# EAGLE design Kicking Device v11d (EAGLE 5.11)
MFG_PART: 74404052470; OC_DIGIKEY: 732-7252-1-ND; OC_FARNELL: 2062831

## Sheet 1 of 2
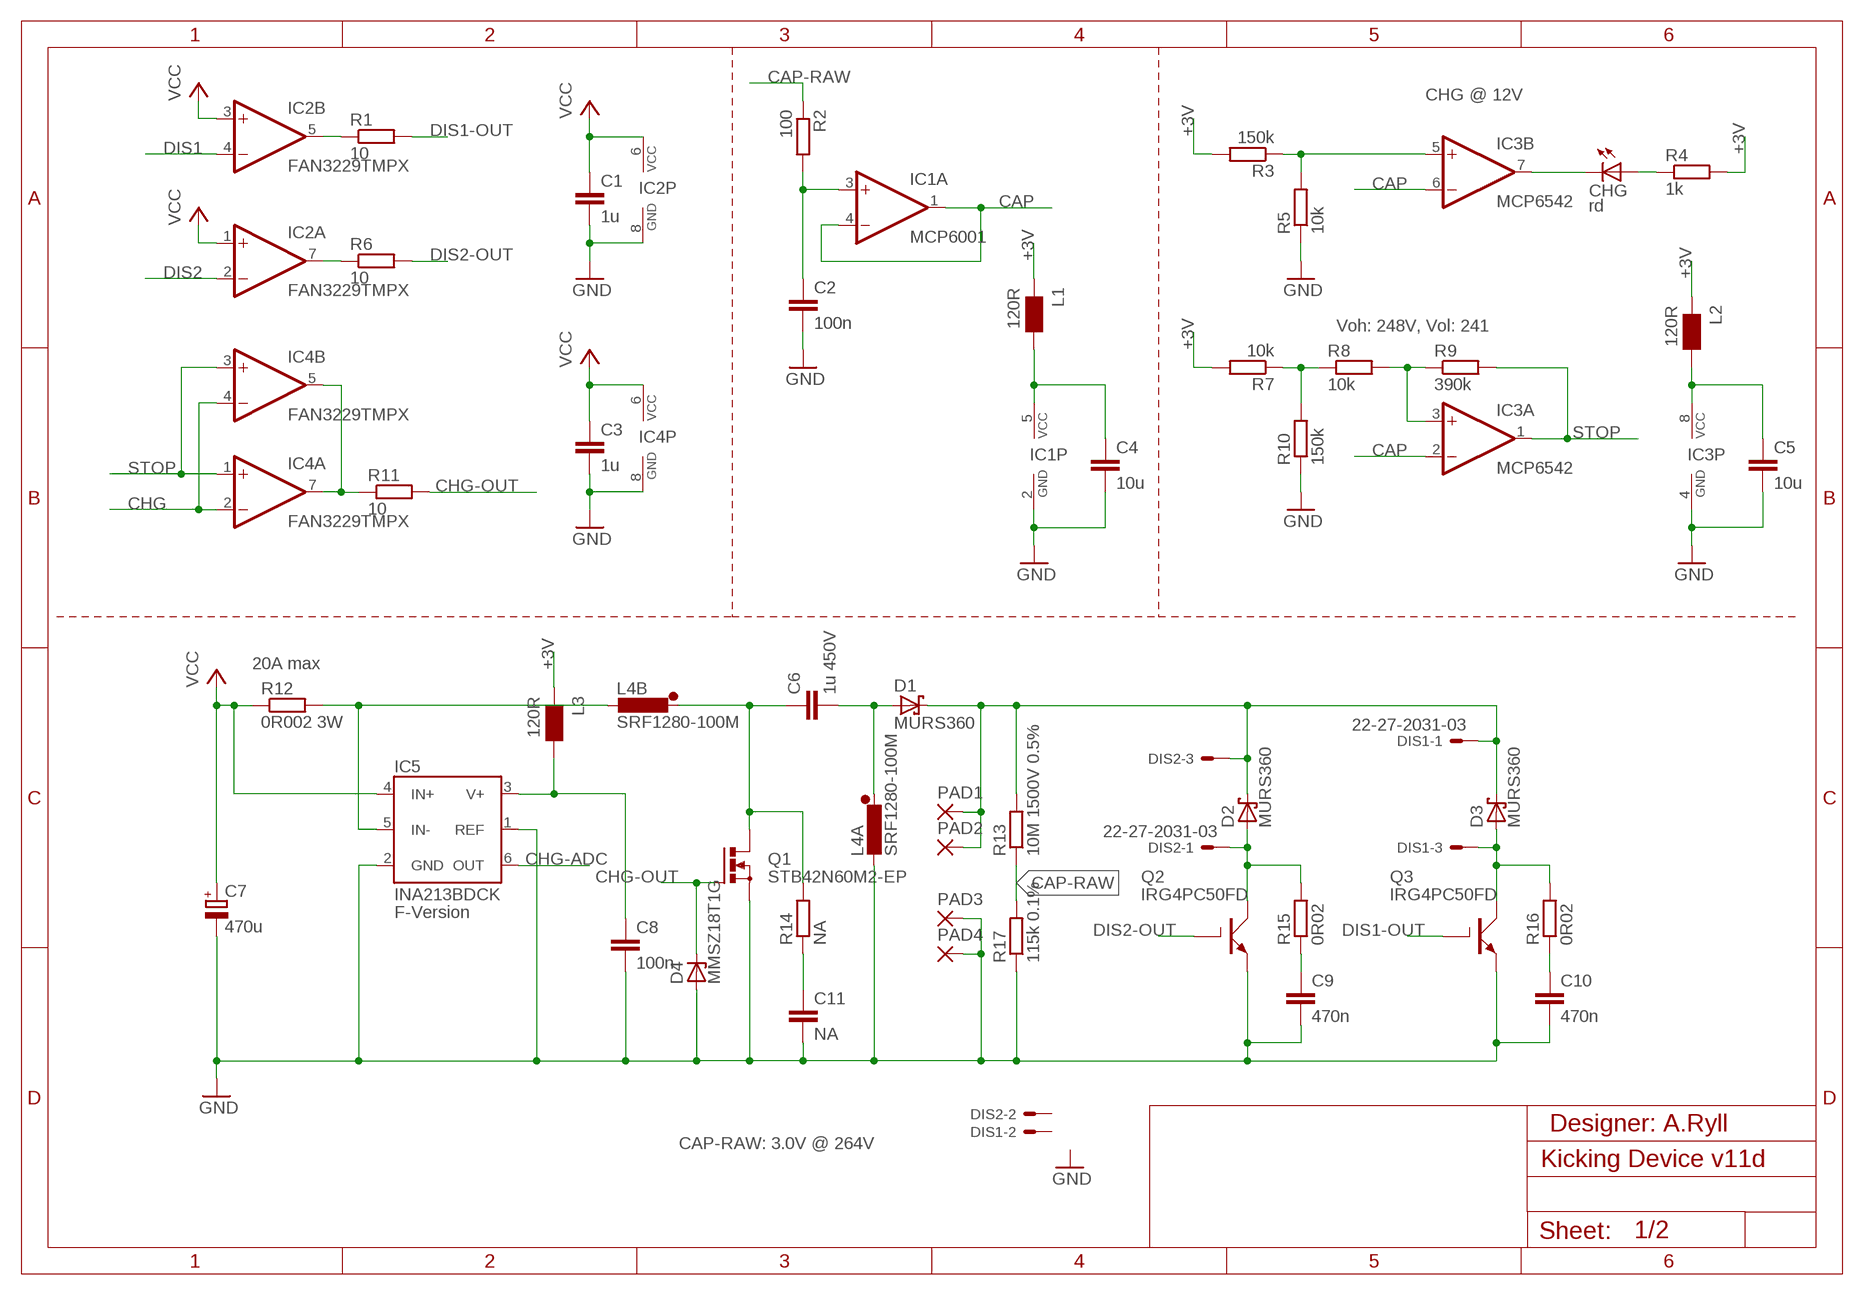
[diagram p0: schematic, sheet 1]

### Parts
C1  1u  C-EUC0603  [C0603]
C2  100n  C-EUC0603  [C0603]
C3  1u  C-EUC0603  [C0603]
C4  10u  C-EUC0603  [C0603]
C5  10u  C-EUC0603  [C0603]
C6  1u 450V  C-EUC2220K  [C2220K]
C7  470u  CPOL-EUG  [PANASONIC_G]
C8  100n  C-EUC0603  [C0603]
C9  470n  C-EUC1812  [C1812]
C10  470n  C-EUC1812  [C1812]
C11  NA  C-EUC1206  [C1206]
CHG  rd  LEDCHIP-LED0603  [CHIP-LED0603]
D1  MURS360  SCHOTTKY-DIODESMC  [SMC]
D2  MURS360  SCHOTTKY-DIODESMC  [SMC]
D3  MURS360  SCHOTTKY-DIODESMC  [SMC]
D4  MMSZ18T1G  ZENER-DIODESOD80C  [SOD80C]
DIS1  22-27-2031-03  [6410-03]
DIS2  22-27-2031-03  [6410-03]
IC1  MCP6001  AD-OP1RT  [SOT23-5]
IC2  FAN3229TMPX  FAN3229_MP  [MLP8]
IC3  MCP6542  AD-OP2M  [MSOP8]
IC4  FAN3229TMPX  FAN3229_MP  [MLP8]
IC5  INA213BDCK  INA21XDCK  [SC70-6L]
L1  120R  WE-CBF_0603  [0603]
L2  120R  WE-CBF_0603  [0603]
L3  120R  WE-CBF_0603  [0603]
L4  SRF1280-100M  SRF1280  [SRF1280]
PAD1  SMD5  [SMD2,54-5,08]
PAD2  SMD5  [SMD2,54-5,08]
PAD3  SMD5  [SMD2,54-5,08]
PAD4  SMD5  [SMD2,54-5,08]
Q1  STB42N60M2-EP  NMOS-D2PAK  [D2PAK]
Q2  IRG4PC50FD  IGBTTO247BV  [TO247BV]
Q3  IRG4PC50FD  IGBTTO247BV  [TO247BV]
R1  10  R-EU_R0603  [R0603]
R2  100  R-EU_R0603  [R0603]
R3  150k  R-EU_R0603  [R0603]
R4  1k  R-EU_R0603  [R0603]
R5  10k  R-EU_R0603  [R0603]
R6  10  R-EU_R0603  [R0603]
R7  10k  R-EU_R0603  [R0603]
R8  10k  R-EU_R0603  [R0603]
R9  390k  R-EU_R0603  [R0603]
R10  150k  R-EU_R0603  [R0603]
R11  10  R-EU_R0603  [R0603]
R12  0R002 3W  R-EU_R2512  [R2512]
R13  10M 1500V 0.5%  R-EU_R1206  [R1206]
R14  NA  R-EU_R1206  [R1206]
R15  0R02  R-EU_R1206  [R1206]
R16  0R02  R-EU_R1206  [R1206]
R17  115k 0.1%  R-EU_R1206  [R1206]

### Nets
400-SW: IC5.5(IN-) L4.P$4 R12.2
+3V: L1.1 L2.1 L3.1 R3.2 R4.2 R7.2 ; also sheet 2
CAP: IC1.1(A:OUT) IC1.4(A:-IN) IC3.2(A:-IN) IC3.6(B:-IN) ; also sheet 2
CAP-RAW: R2.1 R13.1 R17.2
CAPVCC [HV]: D1.C D2.C D3.C DIS1.1 DIS2.3 PAD1.1(P) PAD2.1(P) R13.2
CHG: IC4.2(A:-IN) IC4.4(B:-IN) ; also sheet 2
CHG-ADC: IC5.6(OUT) ; also sheet 2
CHG-OUT: D4.C Q1.1(G) R11.2
CMP-VCC: C5.1 IC3.8(P:VCC) L2.2
DIS1: IC2.4(B:-IN) ; also sheet 2
DIS1-OUT: Q3.1(G) R1.2
DIS1-SW [HV]: D2.A DIS2.1 Q2.2(C) R15.2
DIS2: IC2.2(A:-IN) ; also sheet 2
DIS2-OUT: Q2.1(G) R6.2
DIS2-SW [HV]: D3.A DIS1.3 Q3.2(C) R16.2
GND: C1.2 C2.2 C3.2 C4.2 C5.2 C7.- C8.2 C9.2 C10.2 C11.2 D4.A IC1.2(P:GND) IC2.8(P:GND) IC3.4(P:GND) IC4.8(P:GND) IC5.1(REF) IC5.2(GND) L4.P$3 PAD3.1(P) PAD4.1(P) Q1.3(S) Q2.3(E) Q3.3(E) R5.1 R10.1 R17.1 ; also sheet 2
INA-VCC: C8.1 IC5.3(V+) L3.2
N$2: IC3.5(B:+IN) R3.1 R5.2
N$3: R7.1 R8.1 R10.2
N$4: CHG.C IC3.7(B:OUT)
N$5: IC2.5(B:OUT) R1.1
N$6: CHG.A R4.1
N$8: IC3.3(A:+IN) R8.2 R9.1
N$10: C6.1 L4.P$2 Q1.2(D) R14.2
N$12: C2.1 IC1.3(A:+IN) R2.2
N$13: C6.2 D1.A L4.P$1
N$14: IC4.5(B:OUT) IC4.7(A:OUT) R11.1
N$17: IC2.7(A:OUT) R6.1
N$19: C10.1 R16.1
N$20: C9.1 R15.1
N$21: C11.1 R14.1
OP-VCC: C4.1 IC1.5(P:VCC) L1.2
STOP: IC3.1(A:OUT) IC4.1(A:+IN) IC4.3(B:+IN) R9.2 ; also sheet 2
VCC: C1.1 C3.1 C7.+ IC2.1(A:+IN) IC2.3(B:+IN) IC2.6(P:VCC) IC4.6(P:VCC) IC5.4(IN+) R12.1 ; also sheet 2
Unconnected: DIS1.2 DIS2.2

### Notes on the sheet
- CHG @ 12V
- Voh: 248V, Vol: 241
- 20A max
- F-Version
- Designer: A.Ryll
- CAP-RAW: 3.0V @ 264V

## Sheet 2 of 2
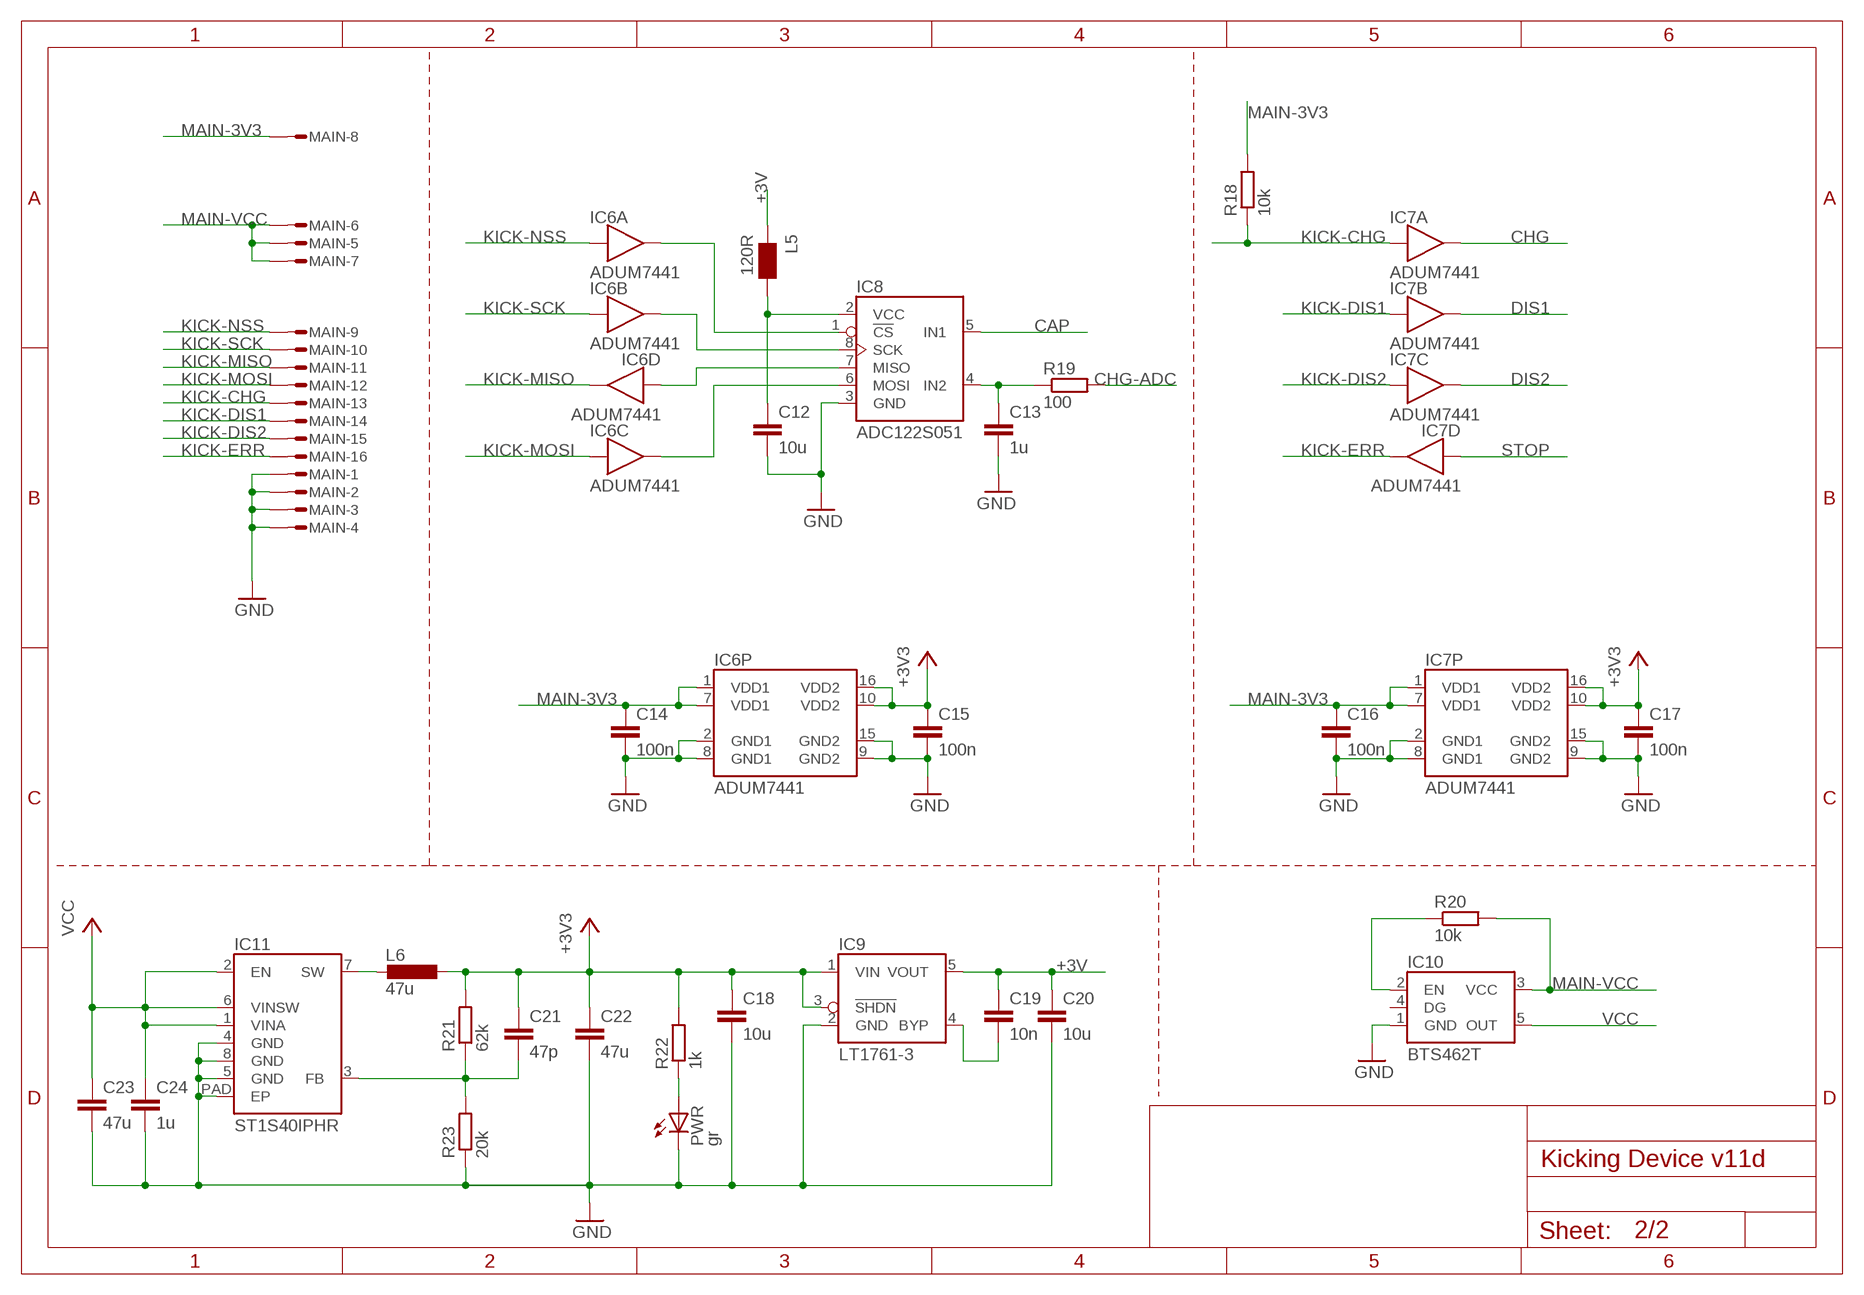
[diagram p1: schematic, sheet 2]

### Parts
C12  10u  C-EUC0603  [C0603]
C13  1u  C-EUC0603  [C0603]
C14  100n  C-EUC0603  [C0603]
C15  100n  C-EUC0603  [C0603]
C16  100n  C-EUC0603  [C0603]
C17  100n  C-EUC0603  [C0603]
C18  10u  C-EUC0603  [C0603]
C19  10n  C-EUC0603  [C0603]
C20  10u  C-EUC0603  [C0603]
C21  47p  C-EUC0603  [C0603]
C22  47u  C-EUC1206  [C1206]
C23  47u  C-EUC1206  [C1206]
C24  1u  C-EUC0603  [C0603]
IC6  ADUM7441  [QSOP16]
IC7  ADUM7441  [QSOP16]
IC8  ADC122S051  ADC__2S__1  [MSOP8]
IC9  LT1761-3  LT1761  [SOT23-5]
IC10  BTS462T  IPS6021R  [TO252-51]
IC11  ST1S40IPHR  [HSOP8]
L5  120R  WE-CBF_0603  [0603]
L6  47u  LLQS  [WE-LQS]
MAIN  MICROMATCH-16SMF  [MMT-F-SMD-16]
PWR  gr  LEDCHIP-LED0603  [CHIP-LED0603]
R18  10k  R-EU_R0603  [R0603]
R19  100  R-EU_R0603  [R0603]
R20  10k  R-EU_R0603  [R0603]
R21  62k  R-EU_R0603  [R0603]
R22  1k  R-EU_R0603  [R0603]
R23  20k  R-EU_R0603  [R0603]

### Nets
+3V: C19.1 C20.1 IC9.5(VOUT) L5.1 ; also sheet 1
+3V3: C15.1 C17.1 C18.1 C21.1 C22.1 IC6.10(P:VDD2) IC6.16(P:VDD2) IC7.10(P:VDD2) IC7.16(P:VDD2) IC9.1(VIN) IC9.3(!SHDN) L6.1 R21.2 R22.2
ADC-VCC: C12.1 IC8.2(VCC) L5.2
CAP: IC8.5(IN1) ; also sheet 1
CHG: IC7.14(A:OUT) ; also sheet 1
CHG-ADC: R19.2 ; also sheet 1
DIS1: IC7.13(B:OUT) ; also sheet 1
DIS2: IC7.12(C:OUT) ; also sheet 1
FB1: C21.2 IC11.3(FB) R21.1 R23.2
GND: C12.2 C13.2 C14.2 C15.2 C16.2 C17.2 C18.2 C20.2 C22.2 C23.2 C24.2 IC6.2(P:GND1) IC6.8(P:GND1) IC6.9(P:GND2) IC6.15(P:GND2) IC7.2(P:GND1) IC7.8(P:GND1) IC7.9(P:GND2) IC7.15(P:GND2) IC8.3(GND) IC9.2(GND) IC10.1(GND) IC11.4(GND) IC11.5(GND) IC11.8(GND) IC11.PAD(EP) MAIN.1 MAIN.2 MAIN.3 MAIN.4 PWR.C R23.1 ; also sheet 1
KICK-CHG: IC7.3(A:IN) MAIN.13 R18.1
KICK-DIS1: IC7.4(B:IN) MAIN.14
KICK-DIS2: IC7.5(C:IN) MAIN.15
KICK-ERR: IC7.6(D:OUT) MAIN.16
KICK-MISO: IC6.6(D:OUT) MAIN.11
KICK-MOSI: IC6.5(C:IN) MAIN.12
KICK-NSS: IC6.3(A:IN) MAIN.9
KICK-SCK: IC6.4(B:IN) MAIN.10
MAIN-3V3: C14.1 C16.1 IC6.1(P:VDD1) IC6.7(P:VDD1) IC7.1(P:VDD1) IC7.7(P:VDD1) MAIN.8 R18.2
MAIN-VCC: IC10.3(VCC) MAIN.5 MAIN.6 MAIN.7 R20.2
N$1: IC6.13(B:OUT) IC8.8(SCK)
N$7: IC6.11(D:IN) IC8.7(MISO)
N$9: PWR.A R22.1
N$11: IC10.2(EN) R20.1
N$15: IC6.12(C:OUT) IC8.6(MOSI)
N$16: IC6.14(A:OUT) IC8.1(!CS)
N$18: C13.1 IC8.4(IN2) R19.1
N$22: C19.2 IC9.4(BYP)
STOP: IC7.11(D:IN) ; also sheet 1
SW1: IC11.7(SW) L6.2
VCC: C23.1 C24.1 IC10.5(OUT) IC11.1(VINA) IC11.2(EN) IC11.6(VINSW) ; also sheet 1
Unconnected: IC10.4(DG)

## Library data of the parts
C1-C6 C8-C24 = rcl:C-EU: CAPACITOR, European symbol
C7 = rcl:CPOL-EU: POLARIZED CAPACITOR, European symbol
CHG PWR = led:LED: LED
D1-D3 = diode:SCHOTTKY-DIODE: Schottky Diode
D4 = diode:ZENER-DIODE: Z-Diode
DIS1 DIS2 = con-molex:22-?-03: CONNECTOR wire to board 2.54 mm (.1 inch) pitch header
IC1 = Marvin:AD-OP1
IC2 IC4 = Marvin:FAN322
IC3 = Marvin:AD-OP2
IC5 = Marvin:INA21X
IC6 IC7 = Marvin:ADUM744
IC8 = Marvin:ADC__2S__1
IC9 = Marvin:LT1761
IC10 = Marvin:IPS60
IC11 = Marvin:ST1S40IP
L1-L3 L5 = wuerth-elektronik:WE-CBF: SMD EMI Suppression Ferrite Beads
L4 = Marvin:SRF
L6 = Marvin:L
MAIN = con-amp-micromatch:MICROMATCH-16: MicroMaTch 16 8-215464-6 / 1-215464-6 Drawing Number C-215464 DDEController.pdf
PAD1-PAD4 = wirepad:SMD5: SMD PAD
Q1 = Marvin:NMOS-D2PAK
Q2 Q3 = Marvin:IGBT
R1-R23 = rcl:R-EU_: RESISTOR, European symbol

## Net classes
0 default: width 0.152 mm, clearance 0.152 mm
1 HV: width 0.203 mm, drill 0.305 mm, clearance 1.016 mm to class 0, clearance 1.016 mm

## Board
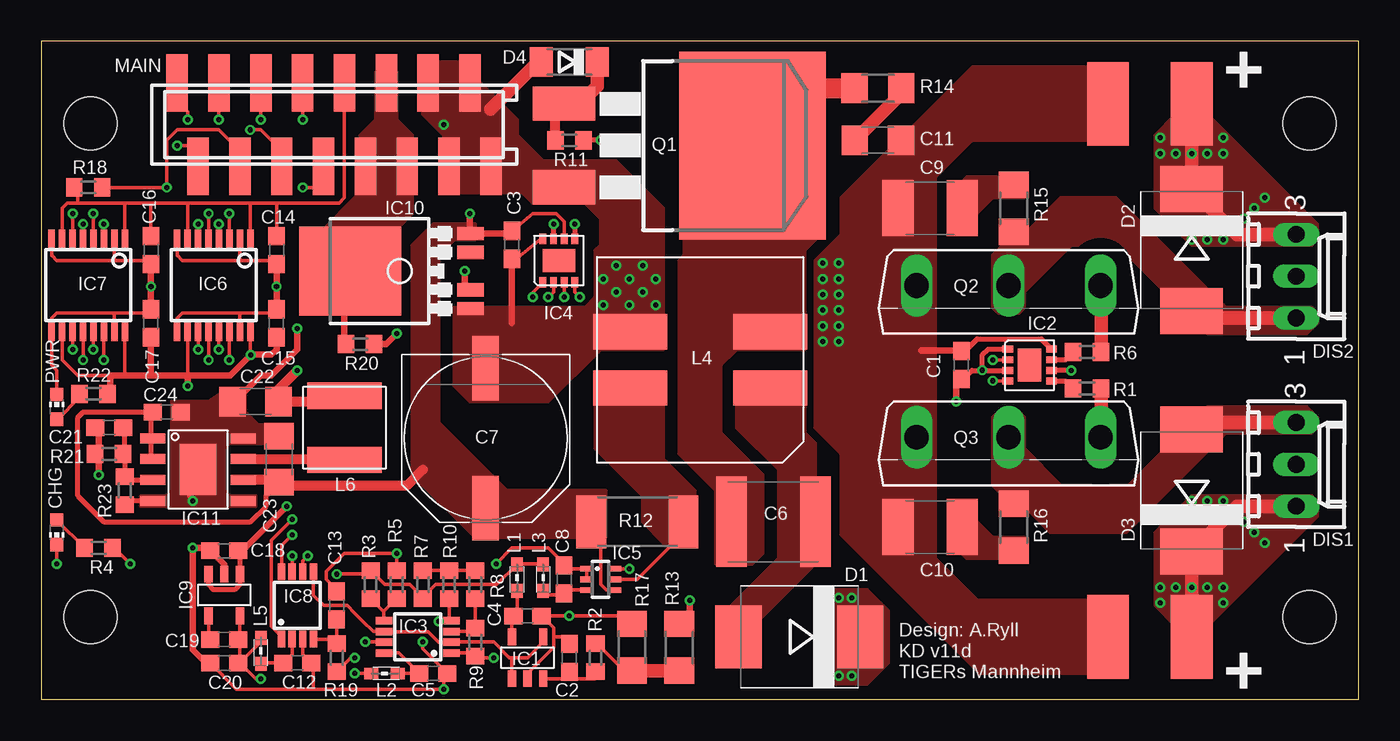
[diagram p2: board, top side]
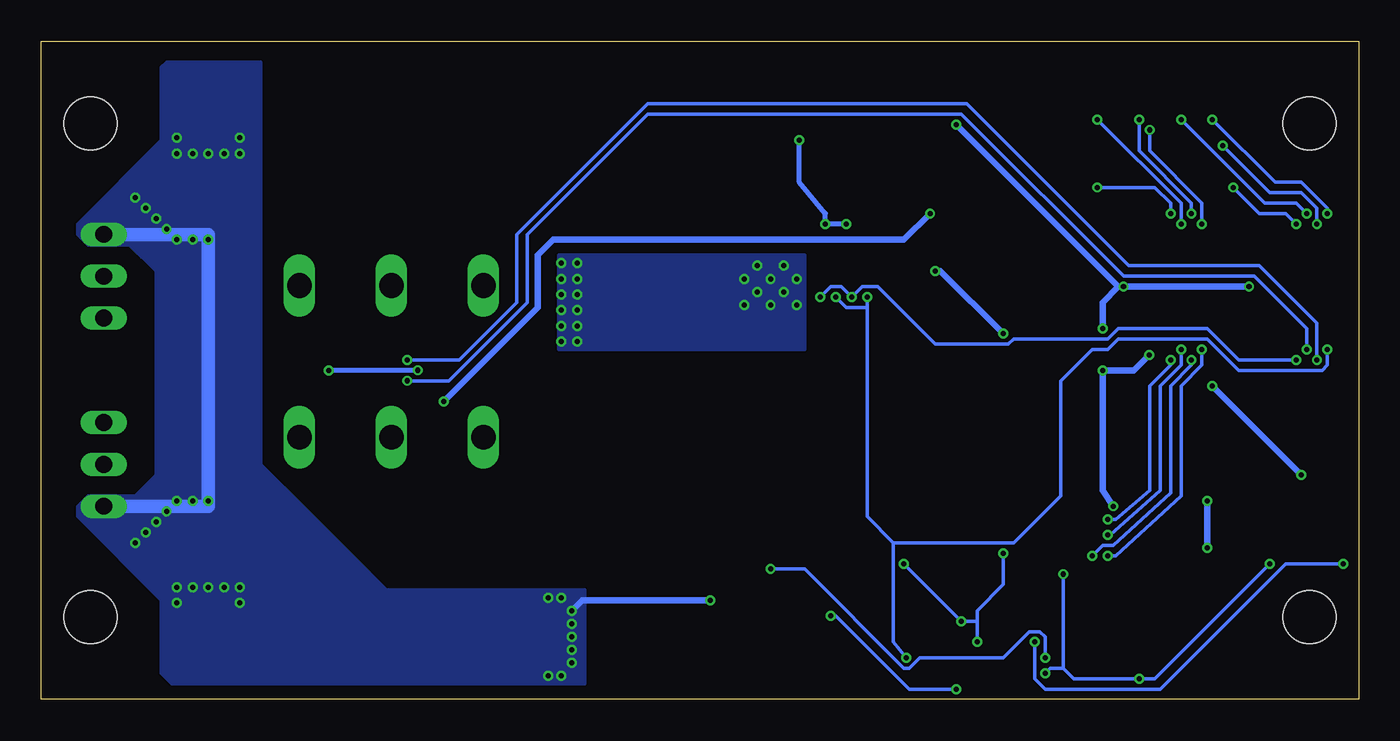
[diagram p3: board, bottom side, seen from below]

Size 80 x 40 mm. Coordinates in mm from the lower left corner, seen from the top.
Outline: 0,0 80,0 80,40 0,40 0,0
Copper layers (1*16): Top 0.035mm / dielectric 1.5mm / Bottom 0.035mm
Design rules "PCB-POOL Standard *": minimum track width 0.15mm, minimum drill 0.3mm, track to track 0.15mm, track to pad 0.15mm, pad to pad 0.15mm, via to via 0.15mm, smd to smd 0.15mm, copper to edge 0.3mm, drill to drill 0.2mm, minimum pad ring 0.2mm, minimum via ring 0.15mm, stop-mask expansion 0.075mm, vias tented up to drill 0mil, thermal gap 0.2mm
Holes 3.2 mm at 77,5 77,35 3,35 3,5
tKeepout: area 74,32 to 80,38; area 74,2 to 80,8; area 0,32 to 6,38; area 0,2 to 6,8; area 50.8,28.9 to 66.7,49.8

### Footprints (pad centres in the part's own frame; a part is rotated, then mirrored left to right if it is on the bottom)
C0603 = smd 1.1 x 1: 1 -0.85,0; 2 0.85,0
C2220K = smd 1.85 x 5.5: 1 -2.55,0; 2 2.55,0
PANASONIC_G = smd 3.9 x 1.6: + 4.25,0; - -4.25,0
C1812 = smd 1.9 x 3.4: 1 -1.95,0; 2 1.95,0
C1206 = smd 1.6 x 1.8: 1 -1.4,0; 2 1.4,0
CHIP-LED0603 = smd 0.8 x 0.8: A 0,-0.75; C 0,0.75
SMC = smd 2.8 x 3.8: A 3.7,0; C -3.7,0
SOD80C = smd 1.4 x 1.8: A 1.7,0; C -1.7,0
6410-03 = drill 1.016 long: 1 2.54,0; 2 0,0; 3 -2.54,0
SOT23-5 = smd 1.016 x 0.508: 1 -1.27,0.953; 2 -1.27,0; 3 -1.27,-0.953; 4 1.27,-0.953; 5 1.27,0.953
MLP8 = smd 0.42 x 0.65: 1 -0.975,-1.325; 2 -0.325,-1.325; 3 0.325,-1.325; 4 0.975,-1.325; 5 0.975,1.325; 6 0.325,1.325; 7 -0.325,1.325; 8 -0.975,1.325 | smd 1.99 x 1.42: 9 0,0
MSOP8 = smd 0.45 x 1: 1 -0.975,-2.05; 2 -0.325,-2.05; 3 0.325,-2.05; 4 0.975,-2.05; 5 0.975,2.05; 6 0.325,2.05; 7 -0.325,2.05; 8 -0.975,2.05
SC70-6L = smd 0.35 x 0.8: 1 -0.65,-0.85; 2 0,-0.85; 3 0.65,-0.85; 4 0.65,0.85; 5 0,0.85; 6 -0.65,0.85
QSOP16 = smd 0.4 x 1.2: 1 -2.223,-2.857; 2 -1.587,-2.857; 3 -0.953,-2.858; 4 -0.318,-2.858; 5 0.318,-2.857; 6 0.953,-2.857; 7 1.587,-2.857; 8 2.223,-2.857; 9 2.223,2.699; 10 1.587,2.699; 11 0.953,2.699; 12 0.318,2.699; 13 -0.318,2.699; 14 -0.953,2.699; 15 -1.587,2.699; 16 -2.223,2.699
TO252-51 = smd 0.8 x 1.6: 1 -2.28,-4.8; 2 -1.14,-4.8; 4 1.14,-4.8; 5 2.28,-4.8 | smd 5.4 x 6.2: 3 0,2.5
HSOP8 = smd 1.524 x 0.61: 1 -2.743,1.905; 2 -2.743,0.635; 3 -2.743,-0.635; 4 -2.743,-1.905; 5 2.743,-1.905; 6 2.743,-0.635; 7 2.743,0.635; 8 2.743,1.905 | smd 2.2 x 3.1: PAD 0,0
0603 = smd 0.85 x 0.7: 1 -0.9,0; 2 0.7,0
SRF1280 = smd 2.15 x 4.5: P$1 1.71,4.25; P$2 -1.71,4.25; P$3 -1.71,-4.25; P$4 1.71,-4.25
WE-LQS = smd 1.6 x 4.5: 1 -1.95,0; 2 1.95,0
MMT-F-SMD-16 = smd 1.3 x 3.5: 1 9.525,-2.54; 2 8.255,2.54; 3 6.985,-2.54; 4 5.715,2.54; 5 4.445,-2.54; 6 3.175,2.54; 7 1.905,-2.54; 8 0.635,2.54; 9 -0.635,-2.54; 10 -1.905,2.54; 11 -3.175,-2.54; 12 -4.445,2.54; 13 -5.715,-2.54; 14 -6.985,2.54; 15 -8.255,-2.54; 16 -9.525,2.54
SMD2,54-5,08 = smd 2.54 x 5.08: 1 0,0
D2PAK = smd 2.083 x 3.81: 1 -2.54,-8.89; 3 2.54,-8.89 | smd 11.43 x 8.89: 2 0,2.54
TO247BV = drill 1.499 long: 1 -5.588,-2.921; 2 0,-2.921; 3 5.588,-2.921
R0603 = smd 1 x 1.1: 1 -0.85,0; 2 0.85,0
R2512 = smd 1.8 x 3.2: 1 -2.8,0; 2 2.8,0
R1206 = smd 1.6 x 1.803: 1 -1.422,0; 2 1.422,0

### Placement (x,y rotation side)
C1  55.88,20.32 90 top
C2  32.07,2.54 90 top
C3  28.57,27.62 270 top
C4  29.53,5.08 0 top
C5  23.81,1.59 0 top
C6  44.45,10.79 0 top
C7  26.99,15.88 270 top
C8  31.75,7.3 90 top
C9  53.98,29.84 180 top
C10  53.98,10.48 180 top
C11  50.8,33.97 0 top
C12  15.56,2.22 0 top
C13  17.94,5.71 90 top
C14  14.29,27.3 270 top
C15  14.29,22.86 90 top
C16  6.67,27.3 270 top
C17  6.67,22.86 90 top
C18  11.11,9.05 180 top
C19  11.11,3.65 180 top
C20  11.11,2.22 180 top
C21  4.13,16.51 0 top
C22  13.02,18.1 180 top
C23  14.45,14.61 90 top
C24  7.62,17.46 0 top
CHG  0.95,10.16 180 top
D1  46.04,3.81 180 top
D2  69.85,27.3 270 top
D3  69.85,12.7 90 top
D4  32.07,38.73 180 top
DIS1  76.2,14.29 270 top
DIS2  76.2,25.72 270 top
IC1  29.53,2.54 90 top
IC2  60.01,20.32 270 top
IC3  22.86,3.81 90 top
IC4  31.43,26.67 0 top
IC5  33.97,7.3 270 top
IC6  10.48,25.08 180 top
IC7  2.86,25.08 180 top
IC8  15.56,5.71 0 top
IC9  11.11,6.35 270 top
IC10  21.27,26.04 90 top
IC11  9.53,13.97 0 top
L1  28.89,7.3 270 top
L2  20.95,1.59 0 top
L3  30.48,7.3 270 top
L4  40.01,20.64 270 top
L5  13.34,2.86 270 top
L6  18.41,16.51 270 top
MAIN  17.78,34.92 0 top
PAD1  69.85,3.81 0 top
PAD2  69.85,36.2 0 top
PAD3  64.77,3.81 0 top
PAD4  64.77,36.2 0 top
PWR  0.95,17.78 0 top
Q1  40.64,33.66 270 top
Q2  58.74,22.23 180 top
Q3  58.74,13.02 180 top
R1  63.5,18.89 0 top
R2  33.66,2.54 270 top
R3  20,6.99 90 top
R4  3.49,9.21 0 top
R5  21.59,6.99 270 top
R6  63.5,21.11 0 top
R7  23.18,6.99 270 top
R8  26.35,6.99 270 top
R9  26.35,3.49 270 top
R10  24.77,6.99 90 top
R11  32.07,33.97 180 top
R12  36.2,10.79 0 top
R13  38.73,3.17 90 top
R14  50.8,37.15 180 top
R15  59.05,29.84 270 top
R16  59.05,10.48 90 top
R17  35.88,3.17 270 top
R18  2.86,31.11 180 top
R19  17.94,2.54 270 top
R20  19.37,21.59 180 top
R21  4.13,14.92 180 top
R22  3.17,18.57 0 top
R23  5.08,12.7 90 top

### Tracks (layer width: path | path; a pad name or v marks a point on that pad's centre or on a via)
400-SW
  Top 0.203: IC5.5 36.2,7.3 38.73,9.84
  pour Top (no thermals): 33.66,19.68 33.66,15.24 36.51,12.38 36.51,10.79 37.78,9.53 39.69,9.53 39.69,12.7 37.78,14.61 37.78,19.68
+3V  (via drill 0.3)
  Top 0.203: 23.18,6.19 22.38,6.99 20.85,6.99 R3.2 19.79,7.62 v17.94,7.62 | 23.18,6.19 R7.2 23.18,6.19 | 23.18,6.19 23.97,6.99 27.68,6.99 L1.1 28.95,8.26 30.43,8.26 L3.1 | v19.05,1.59 L2.1 | 12.06,2.22 C20.1 12.06,2.33 12.06,3.55 C19.1 12.06,3.75 IC9.5 | 12.06,2.22 13.34,3.49 L5.1 | 12.06,2.22 13.02,1.27 v13.34,1.27 | R4.2 4.45,9.21 v5.4,8.26
  Bottom 0.203: 17.94,1.91 v17.94,7.62 | 17.94,1.91 17.3,1.27 v13.34,1.27 12.38,1.27 v5.4,8.26 | v19.05,1.59 18.73,1.91 17.94,1.91
+3V3  (via drill 0.3)
  Top 0.203: 4.18,19.68 2.22,19.68 1.27,20.64 IC7.10 | 5.08,19.68 5.13,19.74 5.08,19.79 IC7.16 | 8.89,19.68 IC6.10 | IC6.16 12.7,21.01 12.75,20.95
  Top 0.305: IC9.3 10.16,6.99 10.48,6.67 11.75,6.67 12.06,6.99 IC9.1 12.06,8.95 C18.1
  Top 0.406: C15.1 14.29,21.27 13.97,20.95 12.75,20.95 v12.73,20.93 11.48,19.68 8.89,19.68 | 8.89,19.68 6.67,19.68 | 6.67,19.68 C17.1 | 6.67,19.68 5.08,19.68 4.18,19.68 4.18,18.73 R22.2 | v3.49,13.65 3.49,14.71 R21.2 3.49,14.92 3.49,16.3 C21.1 | v8.89,19.05 8.89,19.68 | v14.92,11.75 12.22,9.05 C18.1
  Top 0.61: L6.1 18.05,18.1 C22.1 14.42,18.86 v15.56,20
  Bottom 0.406: v12.73,20.93 13.65,20 v15.56,20 15.56,12.7 v14.92,11.75 | v3.49,13.65 v8.89,19.05
ADC-VCC
  Top 0.203: C12.1 14.61,2.12 | IC8.2 15.23,2.75 C12.1 | L5.2 13.4,2.22 C12.1
CAP
  Top 0.203: IC1.4 30.48,3.49 29.53,2.54 28.57,2.54 | 28.57,2.54 28.42,2.54 27.46,3.49 24.92,3.49 IC3.2 24.14,3.48 23.5,4.13 IC3.6 20.15,4.13 19.53,4.76 19.05,5.24 18.57,5.71 17.14,5.71 16.53,6.33 IC8.5 | 28.57,2.54 IC1.1
CAP-RAW
  Top 0.203: 35.4,1.27 35.4,1.75 33.97,3.17 33.87,3.17 R2.1
  Top 0.406: 35.4,1.27 R17.2
  Top 0.813: R17.2 R13.1
CAPVCC  (via drill 0.3)
  Top 0.406: R13.2 39.37,5.08 v39.37,6.03
  Top 0.813: PAD1.1 D3.C 72.6,11.75 DIS1.1 | DIS2.3 72.6,28.26 D2.C PAD2.1
  Bottom 0.406: v39.37,6.03 47.15,6.03 v47.78,5.4
  Bottom 0.813: DIS1.1 69.85,11.75 69.85,28.26 DIS2.3
  other vias: 47.78,3.81 49.21,6.19 48.42,6.19 47.78,4.6 47.78,3.02 67.94,6.83 69.85,6.83 70.8,6.83 68.9,6.83 71.75,6.83 71.75,5.87 67.94,5.87 69.85,33.18 70.8,33.18 71.75,33.18 71.75,34.13 68.9,33.18 67.94,33.18 67.94,34.13 47.78,2.22 48.42,1.43 49.21,1.43 69.85,27.94 70.8,27.94 71.75,27.94 72.39,28.58 73.03,29.21 73.66,29.85 74.3,30.48 69.85,12.07 70.8,12.07 71.75,12.07 72.39,11.43 73.03,10.8 73.66,10.16 74.3,9.53
  pour Top (no thermals): 51.44,2.22 50.16,0.95 47.94,0.95 46.99,1.91 46.99,6.03 47.62,6.67 50.16,6.67 51.44,5.4
  pour Bottom (no thermals): 46.99,6.67 59.05,6.67 66.67,14.29 66.67,38.73 72.39,38.73 72.71,38.42 72.71,33.97 77.79,28.89 77.79,28.26 77.15,27.62 74.61,27.62 73.03,26.04 73.03,13.65 74.3,12.38 77.15,12.38 77.79,11.75 77.79,11.11 72.71,6.03 72.71,1.59 72.07,0.95 46.99,0.95
  pour Top (no thermals): 68.9,4.45 67.63,5.71 67.63,10.16 69.85,12.38 77.15,12.38 77.47,12.06 77.47,11.11 70.8,4.45
  pour Top (no thermals): 68.9,35.56 67.63,34.29 67.63,29.84 69.85,27.62 77.15,27.62 77.47,27.94 77.47,28.89 70.8,35.56
CHG  (via drill 0.3)
  Top 0.203: IC4.2 31.11,25.34 31.11,24.77 v30.8,24.45 | IC7.14 v3.81,20.64 | IC4.4 32.41,24.74 v32.7,24.45
  Bottom 0.203: 4.13,20.64 v3.81,20.64 7.3,20.64 9.21,22.54 14.61,22.54 15.24,21.91 20.95,21.91 21.27,21.59 25.72,21.59 29.21,25.08 30.16,25.08 v30.8,24.45 31.43,25.08 32.07,25.08 v32.7,24.45
CHG-ADC  (via drill 0.3)
  Top 0.203: IC5.6 34.84,7.94 v35.72,7.94 | v19.05,2.54 18.79,2.54 R19.2
  Bottom 0.203: v35.72,7.94 33.66,7.94 27.62,1.91 27.3,1.91 26.67,2.54 21.59,2.54 20,4.13 19.37,4.13 19.05,3.81 v19.05,2.54
CHG-OUT
  Top 0.203: 31.22,35.66 Q1.1
  Top 0.61: R11.2 31.22,35.66
  Top 0.813: D4.C 33.77,37.26 32.7,36.2 Q1.1
CMP-VCC
  Top 0.203: L2.2 C5.1 21.71,2.83 IC3.8
DIS1  (via drill 0.3)
  Top 0.203: 58.74,19.29 IC2.4 58.68,19.37 v57.78,19.37 | IC7.13 3.17,22.15 v3.17,21.27
  Bottom 0.203: v57.78,19.37 55.24,19.37 50.48,24.13 50.48,28.26 43.18,35.56 24.13,35.56 14.29,25.72 6.35,25.72 3.17,22.54 v3.17,21.27
DIS1-OUT
  Top 0.813: R1.2 64.35,15.96 Q3.1
DIS1-SW
  Top 0.813: DIS2.1 70.28,23.18 D2.A
  pour Top (no thermals): 58.1,23.5 57.78,23.81 57.78,26.99 59.37,28.57 60.01,28.57 61.91,30.48 65.25,30.48 71.91,23.81 77.15,23.81 77.47,23.5 77.47,22.86 76.83,22.23 70.8,22.23 65.41,27.62 62.55,27.62 59.69,24.77 59.69,23.81 59.37,23.5
DIS2  (via drill 0.3)
  Top 0.203: IC2.2 v57.78,20.64 | IC7.12 2.54,22.15 v2.54,20.64
  Bottom 0.203: v57.78,20.64 54.61,20.64 51.12,24.13 51.12,28.26 43.18,36.2 23.81,36.2 13.97,26.35 6.03,26.35 2.54,22.86 v2.54,20.64
DIS2-OUT
  Top 0.813: R6.2 64.35,25.12 Q2.1
DIS2-SW
  Top 0.813: DIS1.3 70.28,16.83 D3.A
  pour Top (no thermals): 58.1,17.46 57.78,17.14 57.78,13.02 59.37,11.43 60.01,11.43 61.28,10.16 65.88,10.16 71.91,16.19 77.15,16.19 77.47,16.51 77.47,17.14 76.83,17.78 70.8,17.78 66.04,13.02 61.91,13.02 59.69,15.24 59.69,17.14 59.37,17.46
FB1
  Top 0.305: IC11.3 5.29,13.34 R23.2 5.08,14.82 R21.1 4.98,15.14 5.08,15.24 5.08,16.41 C21.2
GND  (via drill 0.3)
  Top 0.203: IC4.8 30.38,28 28.74,26.67 C3.2 | IC1.2 29.53,1.59 31.11,3.17 31.11,3.81 | IC5.2 IC5.1 31.95,7.95 C8.2 | C8.2 31.65,8.26 | v24.13,4.76 24.89,4.76 IC3.4 24.77,4.93 R10.1 | 31.11,3.81 31.11,4.34 C4.2 30.16,5.29 30.7,5.29 30.8,5.08 v32.07,5.08 35.88,5.08 R17.1 | R5.1 v21.59,8.89 18.41,8.89 17.3,7.78 17.3,7.3 17.94,6.67 C13.2 | 16.51,0.64 16.51,2.12 C12.2 15.88,2.75 IC8.3 | 16.51,0.64 v24.45,0.64 24.45,1.37 C5.2 23.18,3.07 v23.18,3.49 | C17.2 6.45,23.5 4.45,23.5 | 4.45,23.5 0.95,23.5 0.64,23.18 IC7.9 0.64,20.32 0.95,20 PWR.C | 4.45,26.67 6.45,26.67 C16.2 | 4.45,26.67 0.95,26.67 0.64,26.99 IC7.8 | 12.06,26.67 14.07,26.67 C14.2 | 12.06,26.67 8.57,26.67 8.26,26.99 IC6.8 | 12.06,23.5 14.07,23.5 C15.2 | 12.06,23.5 8.57,23.5 8.26,23.18 IC6.9 | 12.06,22.2 IC6.15 12.06,23.5 | 12.06,27.97 IC6.2 12.06,26.67 | 4.45,27.97 IC7.2 4.45,26.67 | C2.2 31.65,3.81 31.11,3.81 | 4.45,23.5 IC7.15 | v27.62,8.26 28.57,9.21 30.8,9.21 31.75,8.26 C8.2 | 16.51,0.64 11.85,0.64 C20.2
  Top 0.305: C1.2 56.2,21.27 56.83,21.91 60.72,21.91 IC2.8 | IC11.4 5.29,12.06 R23.1
  Top 0.406: C17.2 v6.67,25.08 C16.2 | C15.2 v14.29,25.08 C14.2 | 28.57,22.86 C3.2 | v15.56,22.54 15.56,21.27 13.97,19.68 13.34,19.68 11.75,18.1 C22.2 | v9.21,12.06 8.89,12.7 | C20.2 10,2.22 9.21,3.02 v9.21,9.21 10.1,9.21 C18.2 11.11,8.2 IC9.2 | C1.2 55.88,21.19 53.42,21.19
  Top 0.813: 27.18,20.32 C7.- 27.3,20.44 | Q1.3 30.8,31.11 | L4.P$3 35.24,22.86 | D4.A 30.16,38.73 27.3,35.88 | PAD4.1 64.45,35.88
  Bottom 0.203: v23.18,3.49 23.18,4.76 | 23.18,4.76 23.18,5.4 21.59,6.99 v21.59,8.89 | 23.18,4.76 v24.13,4.76 v27.62,8.26 | v24.45,0.64 27.3,0.64 31.75,5.08 v32.07,5.08
  Bottom 0.406: v6.67,25.08 v14.29,25.08 14.61,25.08 | 14.61,25.08 v24.45,34.92 | 14.61,25.08 15.56,24.13 v15.56,22.54 | v9.21,9.21 v9.21,12.06
  other vias: 37.31,23.97 35.72,23.97 34.13,23.97 34.92,26.35 36.51,26.35 37.31,25.56 36.51,24.77 35.72,25.56 34.92,24.77 34.13,25.56 47.47,26.51 47.47,25.56 47.47,24.61 47.47,23.65 47.47,22.7 47.47,21.75 48.42,26.51 48.42,25.56 48.42,24.61 48.42,23.65 48.42,22.7 48.42,21.75
  pour Bottom (no thermals): 33.66,26.99 48.58,26.99 48.58,21.27 33.66,21.27
  pour Top (no thermals): 37.78,21.27 33.97,21.27 30.8,18.1 26.04,18.1 25.08,19.05 25.08,23.81 33.02,23.81 33.66,24.45 33.66,27.3 33.97,27.62 33.97,29.21 33.02,30.16 29.84,30.16 29.21,30.8 24.45,30.8 24.45,34.29 23.18,35.56 23.18,38.73 25.4,38.73 28.89,35.24 28.89,34.29 30.48,32.7 34.92,32.7 37.78,29.84
  pour Top (no thermals): 46.99,26.67 48.58,28.26 48.58,30.48 56.52,38.42 65.72,38.42 65.72,33.97 56.52,33.97 54.29,31.75 54.29,8.57 56.83,6.03 65.72,6.03 65.72,1.59 56.99,1.59 48.58,10 48.58,14.92 46.99,16.51
  pour Top (no thermals): 7.94,18.1 10.16,18.1 11.11,18.73 12.38,18.73 12.38,17.46 13.02,16.83 13.02,16.83 13.18,16.67 14.92,16.67 14.92,15.56 11.43,15.56 11.11,15.24 11.11,12.7 11.43,12.38 13.02,12.38 13.02,11.75 6.03,11.75 6.03,12.38 7.62,12.38 7.94,12.7
INA-VCC
  Top 0.203: IC5.3 31.95,6.65 C8.1 31.65,6.35 30.48,6.35 L3.2
KICK-CHG  (via drill 0.3)
  Top 0.203: IC7.3 3.81,28.03 v3.81,28.89 | MAIN.13 12.06,33.34 10.79,34.61 8.26,34.61 7.62,33.97 v7.62,31.11 R18.1
  Bottom 0.203: v3.81,28.89 4.45,29.53 6.03,29.53 v7.62,31.11
KICK-DIS1  (via drill 0.3)
  Top 0.203: v10.79,35.24 MAIN.14 | IC7.4 3.17,28.02 v3.17,29.53
  Bottom 0.203: v3.17,29.53 3.81,30.16 5.71,30.16 v10.79,35.24
KICK-DIS2  (via drill 0.3)
  Top 0.203: v8.26,33.66 9.53,33.66 MAIN.15 | IC7.5 2.54,28.02 v2.54,28.89
  Bottom 0.203: v2.54,28.89 2.54,29.84 3.49,30.8 5.4,30.8 v8.26,33.66
KICK-ERR  (via drill 0.3)
  Top 0.203: v8.89,35.24 8.89,35.72 8.26,36.35 MAIN.16 | IC7.6 1.91,28.03 v1.91,29.53
  Bottom 0.203: v8.89,35.24 5.08,31.43 3.49,31.43 1.91,29.84 v1.91,29.53
KICK-MISO  (via drill 0.3)
  Top 0.203: MAIN.11 14.61,33.34 13.34,34.61 v12.7,34.61 | IC6.6 9.53,28.03 v9.53,28.89
  Bottom 0.203: v12.7,34.61 12.7,33.34 9.53,30.16 v9.53,28.89
KICK-MOSI  (via drill 0.3)
  Top 0.203: v13.34,35.24 MAIN.12 | IC6.5 10.16,28.02 v10.16,29.53
  Bottom 0.203: v13.34,35.24 13.34,33.34 10.16,30.16 v10.16,29.53 10.16,29.84
KICK-NSS  (via drill 0.3)
  Top 0.203: MAIN.9 17.14,31.11 v15.88,31.11 | IC6.3 11.43,28.03 v11.43,29.53
  Bottom 0.203: v11.43,29.53 11.43,30.16 12.38,31.11 v15.88,31.11
KICK-SCK  (via drill 0.3)
  Top 0.203: v15.88,35.24 MAIN.10 | IC6.4 10.79,28.02 v10.79,28.89
  Bottom 0.203: 10.79,29.21 v10.79,28.89 10.79,30.16 v15.88,35.24
MAIN-3V3
  Top 0.203: 14.29,30.16 C14.1 | 6.67,30.16 C16.1 | 6.67,30.16 8.89,30.16 | 8.89,30.16 12.7,30.16 | 12.7,30.16 14.29,30.16 | 2.22,30.16 1.59,30.16 1.27,29.84 IC7.7 | 2.22,30.16 5.08,30.16 | 5.08,30.16 6.67,30.16 | 14.29,30.16 18.1,30.16 18.41,30.48 MAIN.8 | R18.2 2.22,31.11 2.22,30.16 | 5.08,30.16 IC7.1 | 8.89,30.16 IC6.7 | 12.7,30.16 IC6.1
MAIN-VCC
  Top 0.406: R20.2 18.41,21.69 18.41,24.13 18.77,24.49 IC10.3
  pour Top (no thermals): 15.88,28.57 17.14,28.57 19.05,30.48 19.37,30.8 19.37,34.29 20.32,35.24 20.32,38.1 21.59,38.1 21.59,35.24 22.54,34.29 22.54,29.53 21.59,28.57 21.59,24.77 16.19,24.77 15.88,24.77
N$1  (via drill 0.3)
  Top 0.203: IC8.8 14.61,7.79 14.61,9.37 v15.24,10 | v10.79,21.27 IC6.13
  Bottom 0.203: v15.24,10 15.08,10 12.06,12.7 12.06,19.05 10.79,20.32 v10.79,21.27
N$2
  Top 0.203: 20.81,5.33 R3.1 | IC3.5 20.81,5.33 | R5.2 20.81,5.36 20.81,5.33
N$3
  Top 0.203: R7.1 R10.2 R8.1
N$4  (via drill 0.3)
  Top 0.203: CHG.C v0.95,8.26 | v19.68,3.49 20.8,3.49 IC3.7
  Bottom 0.203: v0.95,8.26 4.45,8.26 12.06,0.64 19.05,0.64 19.68,1.27 v19.68,3.49
N$5
  Top 0.305: IC2.5 62.2,19.34 R1.1
N$6
  Top 0.203: CHG.A 0.95,10.9 R4.1
N$7  (via drill 0.3)
  Top 0.203: IC8.7 15.24,7.77 v15.24,8.73 | v9.53,21.27 IC6.11
  Bottom 0.203: v15.24,8.73 14.76,8.73 10.79,12.38 10.79,19.05 9.53,20.32 v9.53,21.27
N$8
  Top 0.203: IC3.3 26.14,4.13 R9.1 R8.2
N$9
  Top 0.203: PWR.A 1,17.03 2.33,18.36 R22.1
N$10
  Top 0.813: 41.91,10.48 C6.1
  Top 1.219: R14.2 46.67,37.15 Q1.2
  pour Top (no thermals): 39.05,35.88 39.05,26.99 38.73,26.67 38.73,14.92 40.96,12.7 40.96,8.26 43.18,8.26 43.81,8.89 43.81,13.65 41.27,16.19 41.27,20.32 42.23,21.27 46.35,21.27 46.35,27.3 47.31,28.26 47.31,35.88
N$11  (via drill 0.3)
  Top 0.406: IC10.2 25.72,25.25 v25.72,26.04 | R20.1 20.95,21.59 v21.59,22.23
  Bottom 0.406: v21.59,22.23 25.4,26.04 v25.72,26.04
N$12
  Top 0.203: R2.2 33.66,1.27 32.07,1.27 | C2.1 32.07,1.27 | 32.07,1.27 IC1.3
N$13
  pour Top (no thermals): 42.23,19.68 42.23,16.51 44.77,13.97 44.77,8.57 41.59,5.4 41.59,2.54 43.5,2.54 43.5,4.76 46.99,8.26 46.99,15.56 46.35,16.19 46.35,19.68
N$14  (via drill 0.3)
  Top 0.203: 32.38,28.02 IC4.5 | IC4.7
  Top 0.305: IC4.7 v31.11,28.89 | v32.38,28.89 32.38,28.02 | v33.97,33.97 R11.1
  Bottom 0.305: v33.97,33.97 33.97,31.43 32.38,29.53 v32.38,28.89 v31.11,28.89
N$15  (via drill 0.3)
  Top 0.203: IC8.6 15.88,7.77 15.88,8.41 v16.19,8.73 | v10.16,20.64 IC6.12
  Bottom 0.203: v10.16,20.64 10.16,20.32 11.43,19.05 11.43,12.54 14.92,9.37 15.56,9.37 v16.19,8.73
N$16  (via drill 0.3)
  Top 0.203: IC8.1 14.58,3.83 13.97,4.45 13.97,9.68 v15.24,10.95 | v11.43,20.64 IC6.14
  Bottom 0.203: v15.24,10.95 14.76,10.95 12.7,12.7 12.7,19.05 11.43,20.32 v11.43,20.64
N$17
  Top 0.305: IC2.7 62.18,20.64 R6.1
N$18
  Top 0.203: IC8.4 17.66,3.67 R19.1 C13.1
N$19
  pour Top (no thermals): 55.56,11.75 55.88,11.75 57.78,9.84 59.69,9.84 59.69,8.57 56.2,8.57 55.56,9.21
N$20
  pour Top (no thermals): 55.56,28.57 55.88,28.57 57.78,30.48 59.69,30.48 59.69,31.75 56.2,31.75 55.56,31.11
N$21
  Top 0.813: R14.1 52.22,36.79 C11.1
N$22
  Top 0.203: IC9.4 10.16,3.75 C19.2
OP-VCC
  Top 0.203: IC1.5 28.57,4.98 C4.1 28.89,5.29 L1.2
STOP  (via drill 0.3)
  Top 0.203: v27.46,2.54 26.45,2.54 R9.2 26.16,2.83 IC3.1 | IC4.3 31.75,25.34 v31.75,24.45 | IC4.1 29.84,24.73 v29.84,24.45 | v1.91,21.27 IC7.11
  Bottom 0.203: v27.46,2.54 28.26,3.49 28.26,9.53 | 28.26,9.53 20.95,9.53 18.1,12.38 18.1,19.37 16.19,21.27 15.24,21.27 14.61,21.91 9.21,21.91 7.3,20 2.22,20 1.91,20.32 v1.91,21.27 | 28.26,9.53 29.84,11.11 29.84,23.81 | 29.84,23.81 v29.84,24.45 | 29.84,23.81 31.11,23.81 v31.75,24.45
SW1
  Top 0.61: IC11.7 18.37,14.61 L6.2
VCC  (via drill 0.3)
  Top 0.203: IC2.6 | IC4.6 31.75,29.05 31.27,29.53 29.85,29.53 C3.1 | IC5.4 34.3,6.65 33.97,6.99 33.97,10.22 R12.1
  Top 0.305: v62.55,20 IC2.6 | IC2.3 57.32,20 v57.15,20 | IC2.1 57.49,21.3 57.15,20.95 v57.15,20 | C1.1 56.52,20 v57.15,20 | C23.1 13.97,12.73 13.97,12.7 13.65,12.38 13.65,11.75 12.7,10.79 3.81,10.79 2.22,12.38 2.22,17.14 2.54,17.46 C24.1 6.67,17.36 6.67,15.99 IC11.1 6.67,15.76 6.67,14.61 IC11.2
  Top 0.406: v26.04,29.53 26.04,28.32 IC10.5 28.32,28.32 C3.1 | v55.56,18.1 55.56,19.05 C1.1
  Top 0.61: IC11.6 14.32,13.34 C23.1 14.63,13.02 22.23,13.02 23.18,13.97
  Bottom 0.305: v62.55,20 57.31,20 v57.15,20
  Bottom 0.406: v26.04,29.53 27.62,27.94 48.9,27.94 49.85,26.99 49.85,23.81 v55.56,18.1
  pour Top (no thermals): 26.35,27.94 25.08,27.94 24.13,26.99 24.13,16.83 28.26,12.7 34.29,12.7 34.29,9.84 26.35,9.84 22.54,13.65 22.54,27.62 23.81,28.89 26.35,28.89

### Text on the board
tPlace: + | Design: A.Ryll | KD v11d | TIGERs Mannheim | +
